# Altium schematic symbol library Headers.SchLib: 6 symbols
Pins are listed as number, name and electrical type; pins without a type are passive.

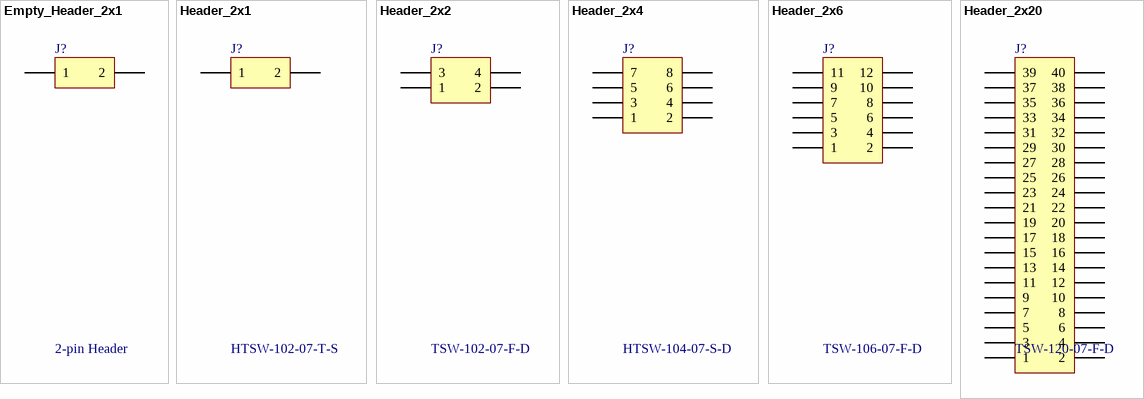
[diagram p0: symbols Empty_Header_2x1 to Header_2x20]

## Empty_Header_2x1
designator J?, comment 2-pin Header
Header, 2 pin
footprint EMPTY_HDR2X1
pins: 1, 2

## Header_2x1
designator J?, comment HTSW-102-07-T-S
Header, 2 pin
footprint HDR2X1
pins: 1, 2

## Header_2x2
designator J?, comment TSW-102-07-F-D
Header, 4 pin
footprint HDR2X2
pins: 1, 2, 3, 4

## Header_2x4
designator J?, comment HTSW-104-07-S-D
Header, 8 pin
footprint HDR2X4
pins: 1, 2, 3, 4, 5, 6, 7, 8

## Header_2x6
designator J?, comment TSW-106-07-F-D
Header, 12 pin
footprint HDR2X6
pins: 1, 2, 3, 4, 5, 6, 7, 8, 9, 10, 11, 12

## Header_2x20
designator J?, comment TSW-120-07-F-D
Header, 40 pin
footprint HDR2X20
pins: 1, 2, 3, 4, 5, 6, 7, 8, 9, 10, 11, 12, 13, 14, 15, 16, 17, 18, 19, 20, 21, 22, 23, 24, 25, 26, 27, 28, 29, 30, 31, 32, 33, 34, 35, 36, 37, 38, 39, 40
